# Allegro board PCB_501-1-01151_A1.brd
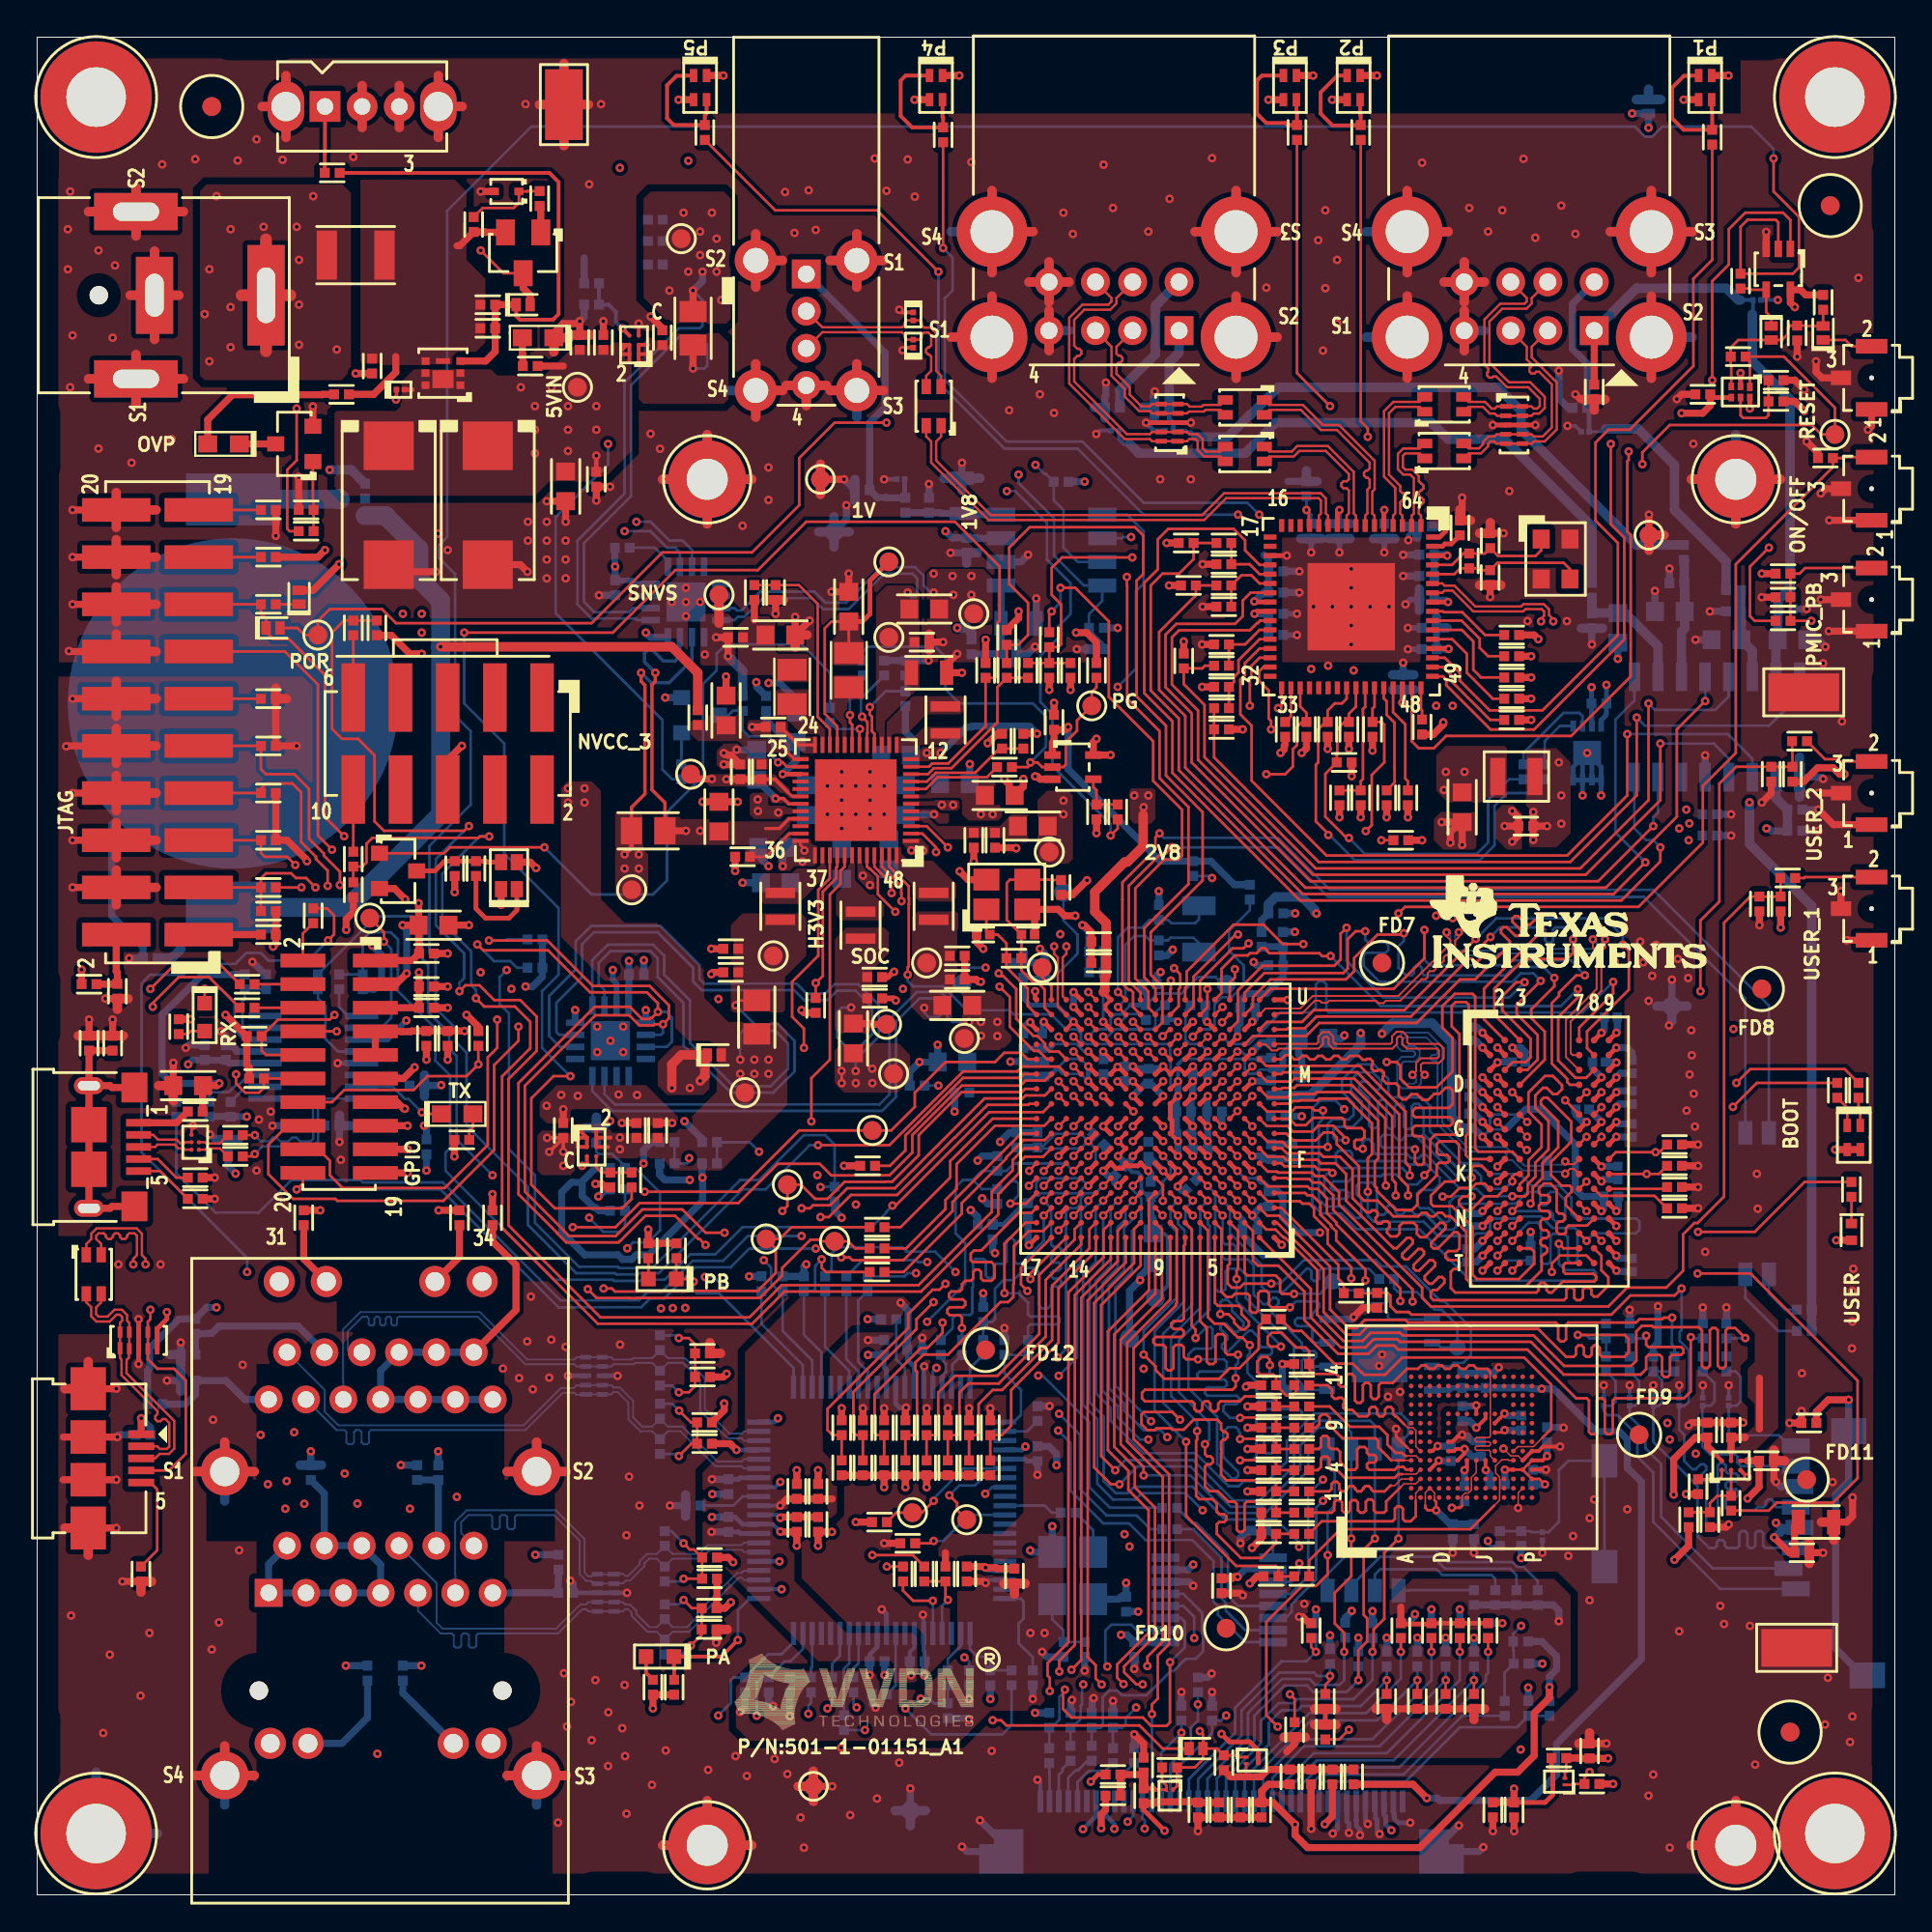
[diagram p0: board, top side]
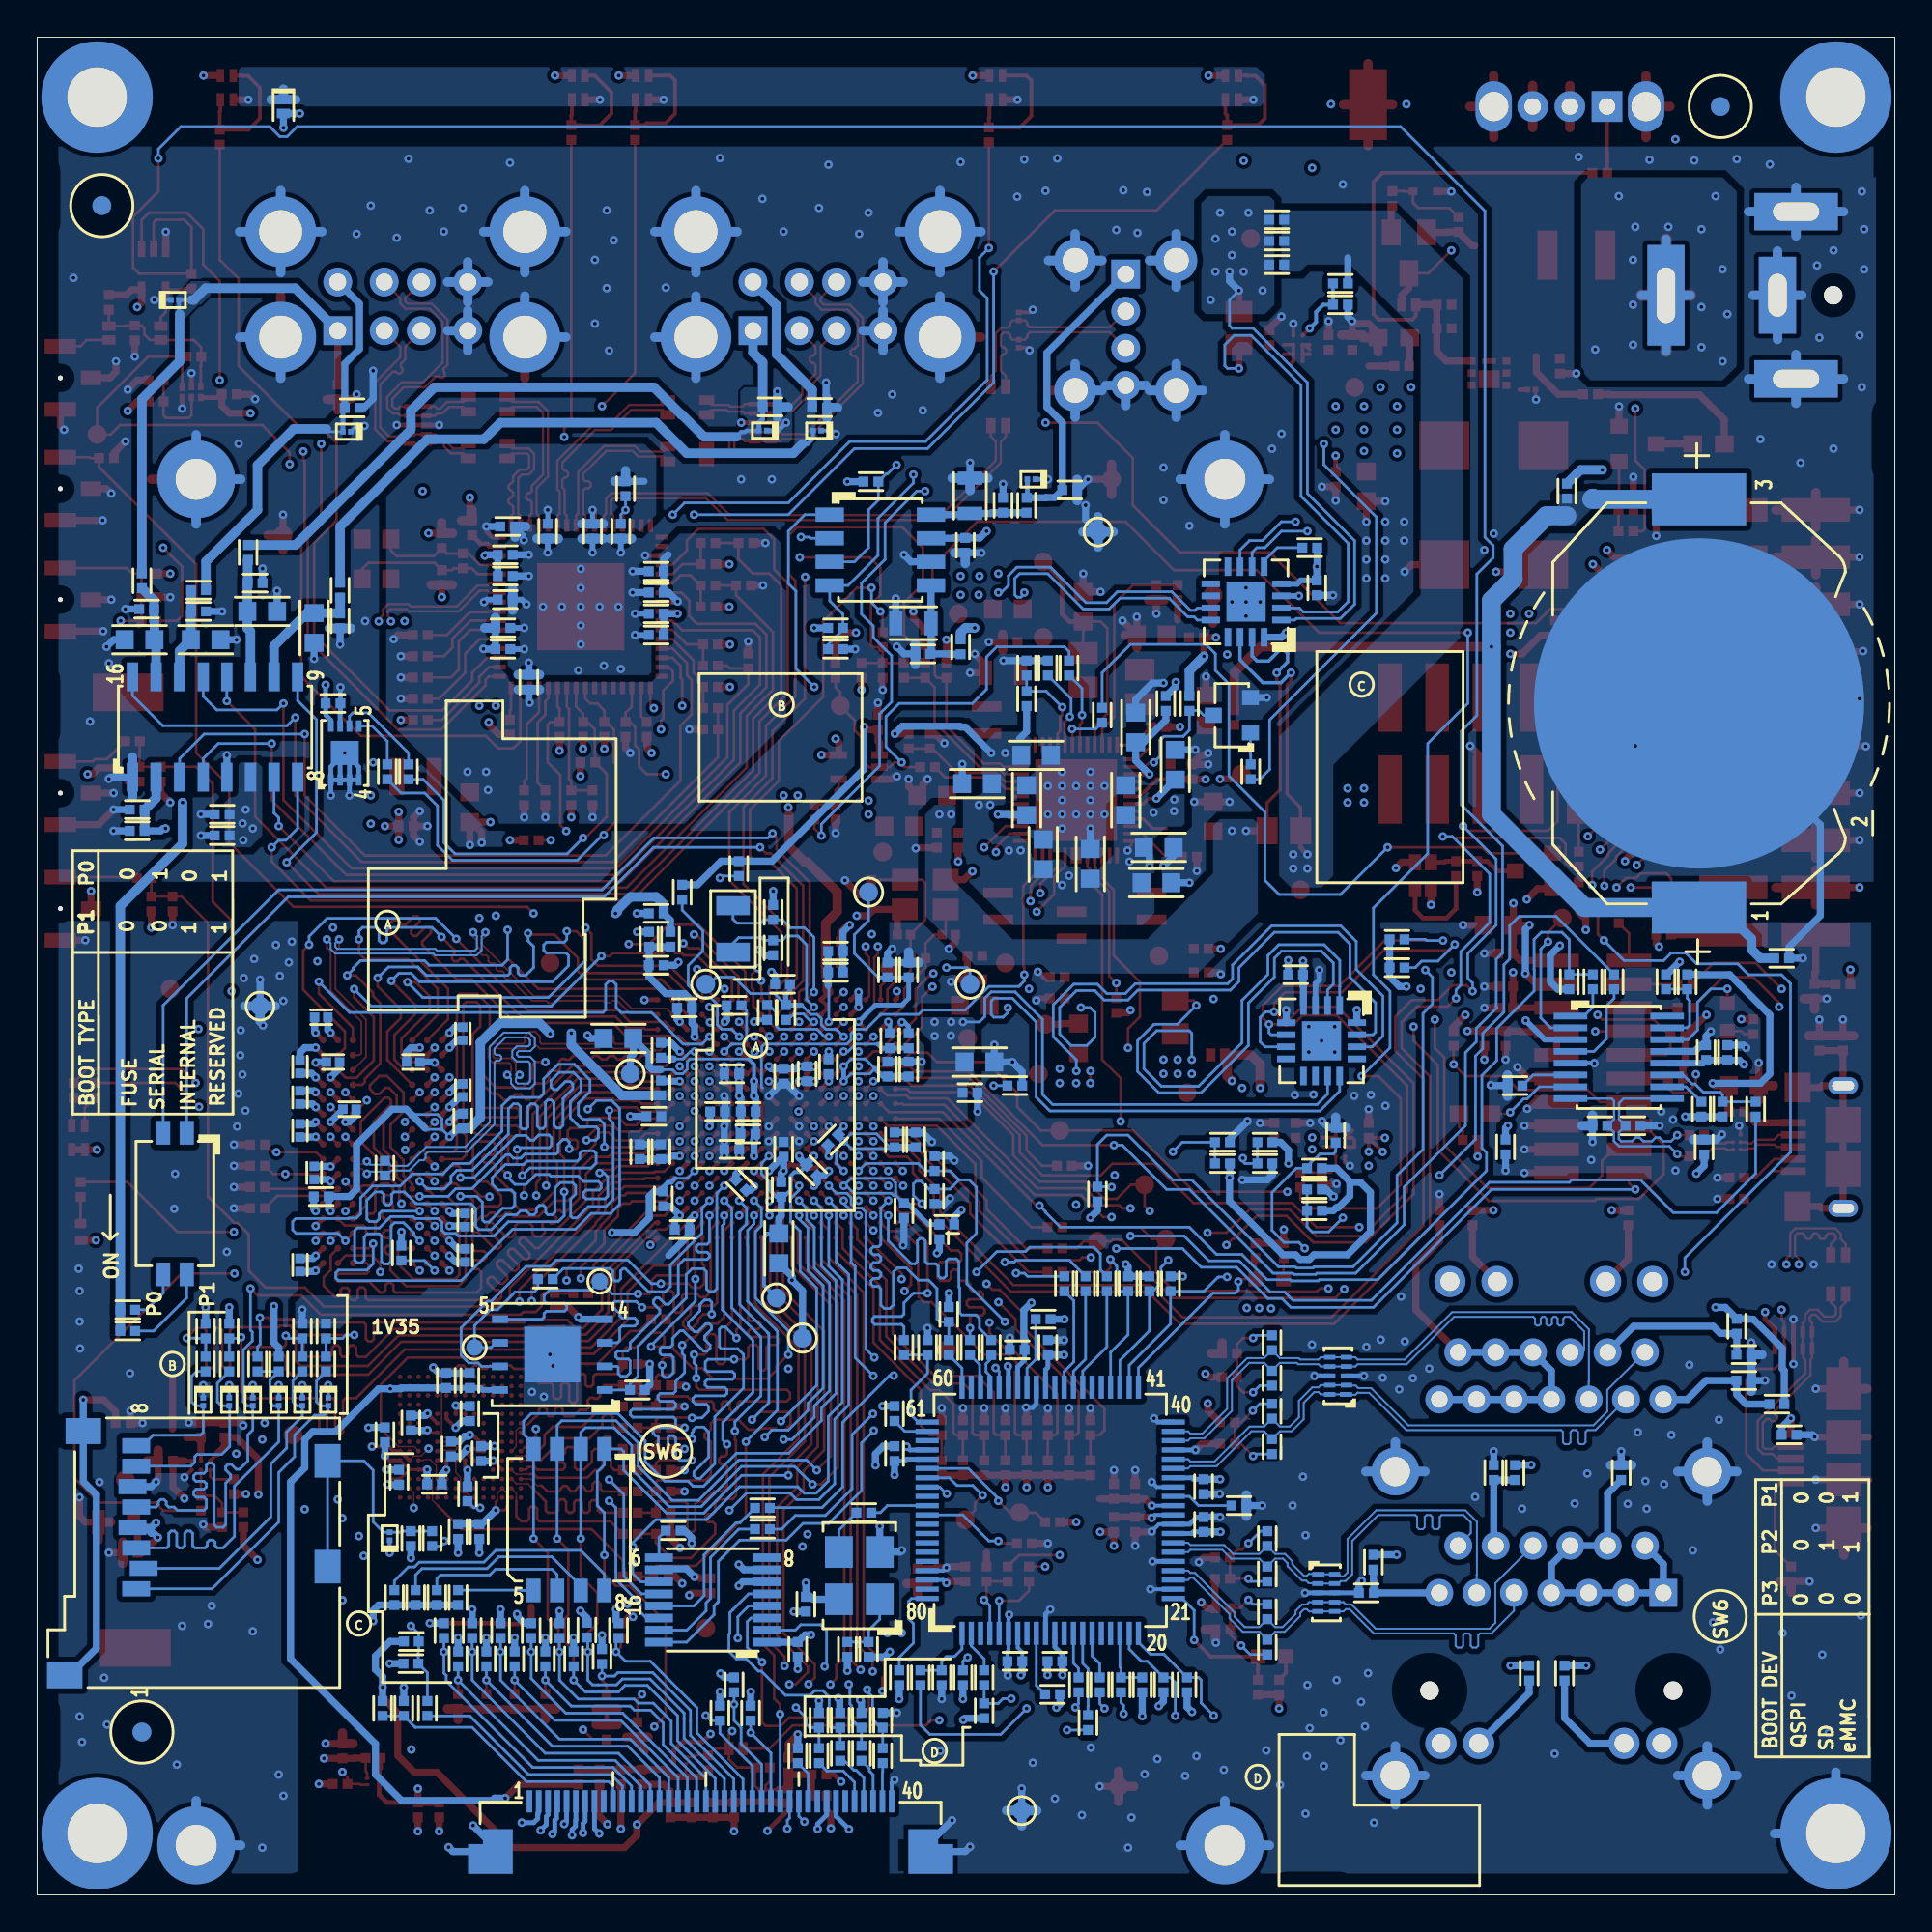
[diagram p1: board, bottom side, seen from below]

Outline 100 x 100 mm; copper layers: TOP, L2_GND, L3_SIG1, L4_SIG2, L5_PWR, BOTTOM. Coordinates in mm from the lower left corner of the outline.
Outline path: 0,100 100,100 100,0 0,0 0,100

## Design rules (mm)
constraint set DEFAULT: min track width 0.142, pair gap 0.152
net group CMD: nets CMD SD2_CMD
net group CRS_DV_A: nets CRS_DV_A PHYA_CRSDV
net group CRS_DV_B: nets CRS_DV_B PHYB_CRSDV
net group DAT0: nets DAT0 SD2_DATA0
net group DAT1: nets DAT1 SD2_DATA1
net group DAT2: nets DAT2 SD2_DATA2
net group DAT3: nets DAT3 SD2_DATA3
net group DAT4: nets DAT4 SD2_DATA4
net group DAT5: nets DAT5 SD2_DATA5
net group DAT6: nets DAT6 SD2_DATA6
net group DAT7: nets DAT7 SD2_DATA7
net group DEBUG_: nets DEBUG_DN DEBUG_DP
net group DEBUG_USB_: nets DEBUG_USB_DN DEBUG_USB_DP
net group DRAM_SDCLK0: nets DRAM_SDCLK0_N DRAM_SDCLK0_P
net group DRAM_SDQS0: nets DRAM_SDQS0_N DRAM_SDQS0_P
net group DRAM_SDQS1: nets DRAM_SDQS1_N DRAM_SDQS1_P
net group OTG_: nets OTG_DM OTG_DP
net group PHYA_MDI_1: nets PHYA_MDI_1_N PHYA_MDI_1_P
net group PHYA_MDI_2: nets PHYA_MDI_2_N PHYA_MDI_2_P
net group PHYA_RXD0: nets PHYA_RXD0 RXD0_A
net group PHYA_RXD1: nets PHYA_RXD1 RXD1_A
net group PHYA_TX_EN: nets ENET1_TXEN PHYA_TX_EN
net group PHYA_TXD0: nets ENET1_TXD0 PHYA_TXD0
net group PHYA_TXD1: nets ENET1_TXD1 PHYA_TXD1
net group PHYB_MDI_1: nets PHYB_MDI_1_N PHYB_MDI_1_P
net group PHYB_MDI_2: nets PHYB_MDI_2_N PHYB_MDI_2_P
net group PHYB_RXD0: nets PHYB_RXD0 RXD0_B
net group PHYB_RXD1: nets PHYB_RXD1 RXD1_B
net group PHYB_TX_EN: nets ENET2_TXEN PHYB_TX_EN
net group PHYB_TXD0: nets ENET2_TXD0 PHYB_TXD0
net group PHYB_TXD1: nets ENET2_TXD1 PHYB_TXD1
net group QSPIA_SCLK: nets QSPIA_SCLK ST_QSPIA_SCLK
net group SD1_CD#: nets SD1_CD# SD1_CD#_R
net group SD1_CLK: nets SD1_CLK SD1_CLK_R
net group SD1_CMD: nets SD1_CMD SD1_CMD_R
net group SD2_CLK: nets SD2_CLK ST_SD2_CLK
net group SDCARD_DAT0: nets SD1_DATA0 SDCARD_DAT0
net group SDCARD_DAT1: nets SD1_DATA1 SDCARD_DAT1
net group SDCARD_DAT2: nets SD1_DATA2 SDCARD_DAT2
net group SDCARD_DAT3: nets SD1_DATA3 SDCARD_DAT3
net group USB: nets USBDN USBDP
net group USB_FL2: nets USBDM_FL2 USBDP_FL2
net group USB_FL3: nets USBDM_FL3 USBDP_FL3
net group USB_FL4: nets USBDM_FL4 USBDP_FL4
net group USB_FL5: nets USBDM_FL5 USBDP_FL5
net group USB_OTG1_: nets USB_OTG1_DN USB_OTG1_DP
net group USB_OTG2_: nets USB_HOST_DN USB_HOST_DP
net group USBD: nets USBDN1_DM USBDN1_DP
net group USBD2: nets USBDM_FL1 USBDP_FL1
net group USBDN2_: nets USBDN2_DM USBDN2_DP
net group USBDN3_: nets USBDN3_DM USBDN3_DP
net group USBDN4_: nets USBDN4_DM USBDN4_DP
net group USBDN5_: nets USBDN5_DM USBDN5_DP
net group 50OHM_2W: nets SD1_VSEL SD2_STROBE SD_VSEL_R STBY_REQ TOUCH_BUSY TOUCH_CS# TOUCH_INTR_REQ# TOUCH_MISO TOUCH_MOSI TOUCH_X+ TOUCH_X- TOUCH_XL TOUCH_XR TOUCH_Y+ TOUCH_Y- TOUCH_YD TOUCH_YU USR_LED1 USR_LED2 USR_LED3
net group CLOCK: nets ENET_REF_CLK JTAG_DACK JTAG_RTCK JTAG_TCK TOUCH_CLOCK
net group DDR_ADDRESS1: nets DRAM_ADDR0 DRAM_ADDR1 DRAM_ADDR2 DRAM_ADDR3 DRAM_ADDR4 DRAM_ADDR5 DRAM_ADDR6 DRAM_ADDR7 DRAM_ADDR8 DRAM_ADDR9 DRAM_ADDR10 DRAM_ADDR11 DRAM_ADDR12 DRAM_ADDR13 DRAM_ADDR14 DRAM_ADDR15 DRAM_CAS# DRAM_CS0# DRAM_CS1# DRAM_ODT0 DRAM_ODT1 DRAM_RAS# DRAM_RESET# DRAM_SDBA0 DRAM_SDBA1 DRAM_SDBA2 DRAM_SDCKE0 DRAM_SDCKE1 DRAM_SDWE#
net group DDR_BYTE(0-7): nets DRAM_DATA0 DRAM_DATA1 DRAM_DATA2 DRAM_DATA3 DRAM_DATA4 DRAM_DATA5 DRAM_DATA6 DRAM_DATA7 DRAM_DQM0
net group DDR_BYTE(8-15): nets DRAM_DATA8 DRAM_DATA9 DRAM_DATA10 DRAM_DATA11 DRAM_DATA12 DRAM_DATA13 DRAM_DATA14 DRAM_DATA15 DRAM_DQM1
net group DEFAULT: nets BASE_CC# BOOST0 BOOST1 BOOT_MODE0 BOOT_MODE1 BUSY CCM_PMIC_STBY_REQ CLOCK_50MHZ COLL_CC# CS# CSENS2_A0 DC34_SEL DC_SW DC_SW_CTL DDR_ZQPAD DEBUG_5V0 DEBUG_RESET# DEBUG_RXD DEBUG_TXD DEBUG_UART_RESET# DRAM_VREF DRAM_ZQPAD ED_EN_A ED_EN_B EEPR_SCL EEPR_SDA ENET_INT_A ENET_INT_B ENETPHY_RESET# EXT_EN FB_DCDC6 FT230_CTS# FT230_RTS# GANG_EN GATE_PMOS GND_DEBUGUSB_CONN GPANIO GPIO1_IO22 GPIO1_IO24 GPIO1_IO25 GPIO3_IO03 GPIO5_IO02 GPIO5_IO03 GPIO5_IO04 GPIO5_IO05 GPIO5_IO06 GPIO5_IO07 GPIO5_IO08 GPIO5_IO09 HUB_CFG_SEL1 HUB_CFG_SEL2 HUB_LEDA1# HUB_LEDA2# HUB_LEDA3# HUB_LEDA4# HUB_LEDA5# HUB_OCS1# HUB_OCS2# HUB_OCS3# HUB_OCS4# HUB_OCS5# HUB_PWR_EN1 HUB_PWR_EN2 HUB_PWR_EN3 HUB_PWR_EN4 HUB_PWR_EN5 HUB_RESET# HUB_VDDA18PLL HUB_VDDDIG18 I2C2_CURSENSE_SCL I2C2_CURSENSE_SDA I2C4_HUB_EEPR_SCL I2C4_HUB_EEPR_SDA I2C4_SCL I2C4_SDATA I.MX_ONOFF INT_LDO IOVDD_LCD IOVDD_LCD_SW_IN JTAG_DE JTAG_MOD JTAG_PWR JTAG_SRST# JTAG_TDI JTAG_TDO JTAG_TMS JTAG_TRST# JTAG_VREF LCD_CS# LCD_IM0 LCD_PWR_EN LCD_RESET# LED_ACT/COL_A LED_ACT/COL_B LED_LINK_A LED_LINK_B LED_SPEED_A LED_SPEED_B LOCAL_PWR MII_MODE_A MII_MODE_B N20222589 N20248573 N20257520 N20264538 N20269907 N20274074 N20274097 N20280334 N20280345 N20323615 N20326291 N20327026 N20327568 N20327935 N20368037 N20387129 N20387131 N20387133 N20387143 N20387145 N20387147 N20429331 N20436944 N20467513 N20496187 N20630241 N20829804 N20866761 N20868982 NVCC_DRAM_1V35 NVCC_DRAM_1V35_SNS NVCC_LCD NVCC_PLL ON_LS4 ON_LS5 OVRPRTC OVRPRTC_LED OVRPRTC_LED_PWR PB_RESET PFBIN PFO# PGOOD PGOOD_BU PHY_MDC PHY_MDIO PMIC_AC_DET PMIC_CC PMIC_GPIO1 PMIC_I2C1_SCL PMIC_I2C1_SDA PMIC_IN_CC# PMIC_INT# PMIC_PB PMIC_PB_B PMIC_PFI PMIC_PFO# PMIC_PGOOD PMIC_PWR_EN PMIC_PWR_EN_R PMIC_STBY_REQ PMIC_WAKE# POR_B PRTDIS_M6 PRTDIS_M7 PRTDIS_P6 PRTDIS_P7 PWR_OV_BASE PWR_OV_CTL PWR_OVP_LED RBIAS RBIAS_HUB RES# RES_LED1 RES_LED2 RES_LED3 REV_CHANGE REVRES_1 REVRES_2 RTC_XTALI RTC_XTALO RXER_A RXER_B RXLED ST_HUB_LEDA1# ST_HUB_LEDA2# ST_HUB_LEDA3# ST_HUB_LEDA4# ST_HUB_LEDA5# SYS_BU SYS_NRST TPS2054_OC1# TPS2054_OC2# TPS2054_OC3# TPS2054_OC4# TXLED UART1_CTS# UART1_RX_DATA UART1_TX_DATA USB2ANY_I2C_SCL USB2ANY_I2C_SDA USB_HOST_ID USB_LDO_DECAP USB_OTG1_CHD# USB_OTG1_FAULT# USB_OTG1_ID USB_OTG1_PWREN USR_B0 USR_B1 USR_BT0 USR_BT1
net group DEFAULT_50E: nets VBUS_DET VBUS_DET_HUB WDOG_ANY X1_ENETPHY XTALI XTALIN_HUB XTALO XTALOUT_HUB
net group EMMC_SIG: nets SD2_RESET#
net group LCD: nets LCD_DATA0 LCD_DATA1 LCD_DATA2 LCD_DATA3 LCD_DATA4 LCD_DATA5 LCD_DATA6 LCD_DATA7 LCD_DATA8 LCD_DATA9 LCD_DATA10 LCD_DATA11 LCD_DATA12 LCD_DATA13 LCD_DATA14 LCD_DATA15 LCD_DATA/COMND LCD_RD_E# LCD_WR_E#
net group LCD2: nets LCD_DATA16 LCD_DATA17 LCD_DATA18 LCD_DATA19 LCD_DATA20 LCD_DATA21 LCD_DATA22 LCD_DATA23
net group PHY_A: nets PHYA_RXER
net group PHY_B: nets PHYB_RXER
net group PWR: nets 3V3_OUT 5VIN DCDC1_L1 DCDC2_L2 DCDC3_L3 DCDC4_L4A DCDC4_L4B DCDC5_L5 DCDC6_L6 N20681531 N20684634 N20685468 N20685796 OTG_PWR VBUS1_FL VBUS2_FL VBUS3_FL VBUS4_FL VBUS5_FL VBUS_DEBUG_USB_5V VCCI_EMMC VDD_1V0 VDD_1V8 VDD_1V8_SNS VDD_ARM_CAP VDD_CENT_TAP_A1 VDD_CENT_TAP_A2 VDD_CENT_TAP_B1 VDD_CENT_TAP_B2 VDD_COINCELL_IN VDD_DCDC6 VDD_ETH_ANA_3V3 VDD_EXT_LS_5V0 VDD_EXT_LS_5V0_SNS VDD_HIGH_CAP VDD_HIGH_IN_3V3 VDD_HIGH_IN_3V3_SNS VDD_HUB_LED VDD_IN_BU VDD_LCD VDD_LCD_BCKLIGHT VDD_LCD_SW_IN VDD_LDO1 VDD_LDO_2V8 VDD_NVCC_3V3 VDD_NVCC_SD1 VDD_OTG1_VBUS VDD_PERI_3V3 VDD_PERI_FIL_3V3 VDD_PMIC_LS_5V0 VDD_PMIC_LS_5V0_SNS VDD_SNVS_CAP VDD_SNVS_IN VDD_SOC_ARM_IN VDD_SOC_ARM_IN_SNS VDD_SOC_CAP VDD_USB_VBUS1 VDD_USB_VBUS2 VDD_USB_VBUS3 VDD_USB_VBUS4 VDD_USB_VBUS5 VIN_PMIC_5V0 VREF_TOUCH_C
net group QSPIA_SIG: nets QSPIA_DATA0 QSPIA_DATA1 QSPIA_DATA2 QSPIA_DATA3 QSPIA_SS0#

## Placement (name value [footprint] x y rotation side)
BH1  BK-912  [BAT3_21P97_21P08X15P24_A1]  10.54 64.13 90 bottom
C1  0.1uF  [0402]  18.03 82.3 270 top
C2  0.01uF  [0402]  24.26 85.6 0 top
C3  100uF  [TCAP_CASED]  24.26 74.8 270 top
C4  22uF  [0603]  28.45 75.82 270 top
C5  1uF  [0402]  30.1 76.2 270 top
C6  4.7uF  [0603]  39.75 54.48 180 bottom
C7  10uF  [0402]  49.53 50.55 0 top
C8  0.1uF  [0402]  49.53 49.28 0 top
C9  0.1uF  [0402]  45.09 48.26 0 top
C10  10uF  [0402]  37.34 50.93 180 top
C11  0.1uF  [0402]  37.34 49.66 180 top
C12  4.7uF  [0603]  45.85 56.01 90 bottom
C13  4.7uF  [0603]  46.23 61.34 180 bottom
C14  4.7uF  [0603]  43.31 55.5 90 bottom
C15  4.7uF  [0603]  39.62 56.39 180 bottom
C16  4.7uF  [0603]  49.4 59.82 0 bottom
C17  4.7uF  [0603]  41.4 58.93 90 bottom
C18  10uF  [0402]  45.09 49.4 0 top
C19  47uF  [0805_B_A1]  48.01 65.79 0 top
C20  0.1uF  [0402]  47.62 67.44 0 top
C21  10uF  [0402]  50.42 56.77 270 top
C22  0.1uF  [0402]  51.56 56.77 270 top
C23  22uF  [0603]  51.82 59.18 0 top
C24  22uF  [0603]  36.7 58.04 90 top
C26  10uF  [0402]  38.99 60.45 90 top
C27  4.7uF  [0603]  46.74 58.93 90 bottom
C28  4.7uF  [0603]  38.73 60.83 90 bottom
C29  0.1uF  [0402]  37.85 60.45 90 top
C30  22uF  [0603]  43.69 69.34 90 top
C31  22uF  [0603]  40.01 67.82 0 top
C32  4.7uF  [0603]  37.08 63.75 90 top
C33  1uF  [0402]  39.62 62.87 180 top
C34  0.1uF  [0402]  37.97 55.88 180 top
C35  10uF  [0402]  33.4 41.15 90 top
C36  1uF  [0402]  32.26 41.15 90 top
C37  4.7uF  [0402]  6.1 50.42 180 bottom
C38  0.1uF  [0402]  28.32 41.15 90 top
C39  2.2uF  [0402]  93.09 23.37 0 top
C40  2.2uF  [0402]  89.92 25.02 90 top
C41  10uF  [0402]  29.21 83.57 90 top
C42  1uF  [0402]  91.19 25.02 90 top
C43  1uF  [0402]  33.66 83.82 90 top
C44  22uF  [0603]  49.28 44.83 180 bottom
C45  0.22uF  [0402]  59.82 44.07 90 bottom
C46  0.22uF  [0402]  59.94 37.97 90 bottom
C47  0.22uF  [0402]  58.29 38.99 225 bottom
C48  22uF  [0603]  60.07 34.8 270 bottom
C49  4.7uF  [0402]  49.78 43.18 180 bottom
C50  0.22uF  [0402]  59.82 40.13 270 bottom
C51  0.22uF  [0402]  61.72 42.16 0 bottom
C52  0.22uF  [0402]  61.74 40.96 0 bottom
C53  0.22uF  [0402]  58.55 44.2 90 bottom
C54  22uF  [0603]  68.71 46.1 0 bottom
C55  4.7uF  [0402]  54.1 45.97 90 bottom
C56  0.22uF  [0402]  53.09 45.97 90 bottom
C57  10uF  [0402]  54.23 49.78 90 bottom
C58  0.22uF  [0402]  53.09 49.78 90 bottom
C59  0.22uF  [0402]  59.88 49.02 0 bottom
C60  10uF  [0402]  59.69 47.5 270 bottom
C61  0.22uF  [0402]  60.71 47.5 270 bottom
C62  0.22uF  [0402]  57.4 44.58 270 bottom
C63  0.22uF  [0402]  84.71 37.59 0 bottom
C64  0.22uF  [0402]  77.09 41.66 90 bottom
C65  10uF  [0402]  66.8 41.91 0 bottom
C66  0.22uF  [0402]  63.37 42.16 0 bottom
C67  0.22uF  [0402]  67.56 40.01 270 bottom
C68  0.22uF  [0402]  66.42 40.01 270 bottom
C69  0.22uF  [0402]  62.61 40.13 180 bottom
C70  0.22uF  [0402]  62.61 44.2 180 bottom
C71  0.22uF  [0402]  66.42 43.43 90 bottom
C72  0.22uF  [0402]  62.48 47.88 0 bottom
C73  0.22uF  [0402]  65.15 47.75 0 bottom
C74  1uF  [0201]  76.96 34.42 90 bottom
C75  1uF  [0201]  85.09 38.86 90 bottom
C76  1uF  [0201]  83.19 42.29 0 bottom
C77  1uF  [0201]  85.85 41.15 90 bottom
C78  0.1uF  [0201]  84.71 47.24 0 bottom
C79  0.1uF  [0201]  84.07 44.83 180 bottom
C80  0.1uF  [0201]  85.85 42.93 270 bottom
C81  0.1uF  [0201]  76.96 36.32 90 bottom
C82  0.1uF  [0201]  77.09 43.31 90 bottom
C83  0.1uF  [0201]  77.09 46.35 270 bottom
C84  0.1uF  [0201]  85.85 44.58 90 bottom
C85  0.1uF  [0201]  85.85 33.91 270 bottom
C86  0.1uF  [0201]  79.76 44.83 0 bottom
C87  4.7uF  [0402]  66.68 52.83 0 bottom
C88  0.1uF  [0402]  66.68 50.04 180 bottom
C89  0.22uF  [0402]  53.34 36.83 270 bottom
C90  0.22uF  [0402]  62.11 38.21 45 bottom
C91  0.22uF  [0402]  57.15 40.64 315 bottom
C92  0.22uF  [0402]  65.28 35.81 0 bottom
C93  18pF  [0402]  72.14 32 270 top
C94  10uF  [0402]  57.15 51.31 180 top
C95  10uF  [0402]  57.15 50.16 180 top
C96  0.22uF  [0402]  66.29 37.47 270 bottom
C97  10uF  [0402]  57.02 50.8 180 bottom
C98  0.1uF  [0402]  57.02 49.66 180 bottom
C99  0.22uF  [0402]  52.7 40.64 90 bottom
C100  10uF  [0402]  53.09 44.45 90 bottom
C101  0.1uF  [0402]  54.23 44.45 90 bottom
C102  0.22uF  [0402]  53.85 40.64 90 bottom
C103  0.1uF  [0402]  77.72 24 90 bottom
C104  0.1uF  [0402]  79.88 25.4 270 bottom
C105  2.2uF  [0402]  76.71 25.91 90 bottom
C106  0.1uF  [0402]  76.1 23.75 270 bottom
C107  0.1uF  [0402]  81.28 24.77 90 bottom
C108  0.1uF  [0402]  78.61 22.1 180 bottom
C109  2.2uF  [0402]  80.52 22.48 90 bottom
C110  1uF  [0402]  77.34 19.56 270 bottom
C111  0.1uF  [0402]  76.2 19.56 270 bottom
C112  10uF  [0402]  76.71 27.69 90 bottom
C113  0.22uF  [0402]  77.98 27.69 90 bottom
C114  47uF  [0805_B_A1]  95.76 20.07 0 top
C115  0.1uF  [0402]  95 18.41 0 top
C116  0.1uF  [0402]  40.89 19.94 270 top
C117  10uF  [0402]  52.61 17.16 90 top
C118  0.1uF  [0402]  45.21 12.57 0 bottom
C119  0.1uF  [0402]  53.85 23.75 90 bottom
C120  0.1uF  [0402]  50.04 17.27 90 top
C121  0.1uF  [0402]  45.59 29.46 90 bottom
C122  0.1uF  [0402]  28.45 16.26 180 bottom
C123  0.1uF  [0402]  21.59 22.73 270 bottom
C124  0.1uF  [0402]  8.13 27.69 0 bottom
C125  0.1uF  [0402]  8.13 29.08 0 bottom
C126  10uF  [0402]  40.89 21.72 90 top
C127  0.1uF  [0402]  42.04 21.72 90 top
C128  0.1uF  [0402]  84.07 64.13 180 bottom
C129  33pF  [0402]  78.22 72.9 90 top
C130  33pF  [0402]  78.21 70.91 270 top
C131  1uF  [0402]  66.68 71.25 0 bottom
C132  1uF  [0402]  74.8 72.14 180 bottom
C133  0.1uF  [0402]  66.68 70.1 0 bottom
C134  0.1uF  [0402]  74.8 70.99 180 bottom
C135  1uF  [0402]  66.68 67.82 0 bottom
C136  0.1uF  [0402]  66.68 68.96 0 bottom
C137  0.1uF  [0402]  73.53 65.28 90 bottom
C138  0.1uF  [0402]  74.68 73.66 180 bottom
C139  0.1uF  [0402]  70.1 73.41 270 bottom
C140  0.1uF  [0402]  74.8 69.72 180 bottom
C141  0.1uF  [0402]  74.93 67.06 180 bottom
C142  0.1uF  [0402]  72.52 73.41 270 bottom
C143  1uF  [0402]  74.93 68.2 180 bottom
C149  22uF  [0603]  94.49 67.56 0 bottom
C150  0.1uF  [0402]  94.11 69.22 0 bottom
C151  22uF  [0603]  90.93 67.56 180 bottom
C152  0.1uF  [0402]  91.31 69.09 180 bottom
C153  22uF  [0603]  87.88 69.09 180 bottom
C154  0.1uF  [0402]  88.26 70.61 180 bottom
C155  22uF  [0603]  85.09 68.2 270 bottom
C156  0.1uF  [0402]  83.69 68.58 270 bottom
C157  10uF  [0402]  94.62 57.28 0 bottom
C158  0.1uF  [0402]  94.62 58.42 0 bottom
C159  10uF  [0402]  90.04 57.02 0 bottom
C160  0.1uF  [0402]  90.04 58.17 0 bottom
C161  0.1uF  [0402]  63.75 65.02 180 top
C162  0.1uF  [0402]  63.75 67.31 180 top
C163  0.1uF  [0402]  63.88 69.34 180 top
C164  0.1uF  [0402]  63.88 71.63 180 top
C165  0.1uF  [0402]  50.04 72.64 270 bottom
C166  47uF  [0805_B_A1]  49.78 75.31 90 bottom
C167  0.1uF  [0402]  48.01 74.8 270 bottom
C168  47uF  [0805_B_A1]  52.83 68.45 0 bottom
C169  0.1uF  [0402]  52.32 66.8 180 bottom
C170  0.1uF  [0402]  9.02 45.34 90 bottom
C171  0.1uF  [0402]  10.16 45.34 90 bottom
C172  4.7uF  [0402]  20.96 40.26 270 bottom
C173  0.1uF  [0402]  10.27 40.25 90 bottom
C174  4.7uF  [0603]  8.13 43.56 180 top
C175  47pF  [0402]  15.88 41.4 0 bottom
C176  47pF  [0402]  14.1 41.4 180 bottom
C177  0.1uF  [0402]  4.06 45.85 90 top
C180  0.1uF  [0402]  32.26 49.53 0 bottom
C181  0.1uF  [0402]  31.12 70.36 270 bottom
C182  4.7uF  [0402]  62.48 4.57 270 top
C183  4.7uF  [0402]  65.91 4.57 270 top
C184  10uF  [0402]  59.56 6.98 90 top
C185  0.1uF  [0402]  63.63 4.57 270 top
C186  10uF  [0402]  68.58 6.35 270 top
C187  0.1uF  [0402]  64.77 4.57 270 top
C188  0.22uF  [0402]  59.05 13.21 270 bottom
C189  0.1uF  [0402]  65.76 19.61 0 bottom
C190  0.1uF  [0402]  63.75 16.64 270 top
C191  18pF  [0402]  57.91 9.4 270 bottom
C192  18pF  [0402]  55.63 9.4 270 bottom
C193  18pF  [0402]  54.48 9.4 270 bottom
C194  18pF  [0402]  56.77 9.4 270 bottom
C195  1uF  [0402]  92.71 53.34 270 top
C196  1uF  [0402]  93.34 60.32 270 top
C197  4.7uF  [0402]  78.36 4.57 270 top
C198  10uF  [0402]  83.57 7.75 90 top
C199  0.1uF  [0402]  79.5 4.57 270 top
C200  15pF  [0402]  60.38 50.98 270 bottom
C201  15pF  [0402]  60.38 52.89 90 bottom
C204  12pF  [0201]  53.34 51.69 0 top
C205  12pF  [0201]  50.93 51.69 180 top
C572  0.1uF  [0402]  4.32 48.64 270 top
C573  0.1uF  [0402]  89.66 80.77 180 top
C574  0.1uF  [0402]  47.24 29.34 0 bottom
C575  0.1uF  [0402]  37.21 19.94 90 bottom
C576  0.1uF  [0402]  37.21 21.97 270 bottom
C577  0.1uF  [0402]  47.37 12.57 0 bottom
C583  4.7uF  [0603]  21.34 52.2 0 top
C584  0.1uF  [0402]  20.96 50.67 0 top
C585  1uF  [0402]  20.96 48.9 0 top
C586  0.1uF  [0402]  20.96 47.75 0 top
C587  1uF  [0402]  22.1 46.1 270 top
C588  0.1uF  [0402]  20.96 46.1 270 top
C589  4.7uF  [0603]  76.71 58.55 270 top
C590  220uF  [TCAP_CASEE]  18.92 74.8 270 top
C591  0.1uF  [0402]  36.2 18.16 180 top
C592  0.1uF  [0402]  36.17 14.29 180 top
C593  0.1uF  [0402]  35.92 24.29 180 top
C594  0.1uF  [0402]  35.81 29.15 180 top
C596  1uF  [0402]  30.48 83.57 90 top
C597  10uF  [0402]  80.14 57.53 180 top
C598  0.1uF  [0402]  96.27 77.34 180 top
C599  0.1uF  [0402]  94.74 84.07 270 top
C600  4.7uF  [0603]  40.86 62.84 90 bottom
C601  0.1uF  [0402]  83.82 80.9 90 top
C602  0.1uF  [0402]  83.04 80.04 0 bottom
C603  0.1uF  [0402]  60.54 80.1 0 bottom
C604  0.1uF  [0402]  57.88 80.06 0 bottom
C605  0.1uF  [0402]  44.41 75.62 0 bottom
C606  0.1uF  [0402]  5.7 24.77 0 bottom
C607  0.01uF  [0402]  58.62 15.65 270 bottom
D1  MM5Z5V1S  [DIO_SOD-523_A1]  25.27 91.69 180 top
D2  CDBQR0130L  [DIO-0402]  26.16 85.6 0 top
D4  R  [LED-0603]  10.03 78.1 180 top
D5  G  [LED-0603]  26.97 83.82 180 top
D6  CDBQR0130L  [DIO-0402]  36.45 45.21 0 top
D7  Y  [LED-0603_C_A1]  33.53 12.83 180 top
D8  Y  [LED-0603_C_A1]  33.66 33.15 180 top
D9  CDBQR0130L  [DIO-0402]  86.74 96.27 270 bottom
D10  G  [LED-0603]  22.61 42.04 0 top
D11  Y  [LED-0603_C_A1]  9.02 47.24 270 top
D12  CDBQR0130L  [DIO-0402]  62.38 7.87 0 top
D15  O  [LED2_0P9_1X0P6]  97.66 35.69 90 top
D26  CDBQR0130L  [DIO-0402]  12.7 68.2 0 top
D27  CDBQR0130L  [DIO-0402]  96.14 84.07 90 top
D28  CDBQR0130L  [DIO-0402]  93.34 84.07 270 top
D29  CDBQR0130L  [DIO-0402]  14.1 69.85 90 top
DA1  HSMF-C165  [LED4_0P7_1P6X0P8]  89.79 97.28 90 top
DA2  HSMF-C165  [LED4_0P7_1P6X0P8]  70.87 97.28 90 top
DA3  HSMF-C165  [LED4_0P7_1P6X0P8]  67.44 97.28 90 top
DA4  HSMF-C165  [LED4_0P7_1P6X0P8]  48.39 97.28 90 top
DA5  HSMF-C165  [LED4_0P7_1P6X0P8]  35.69 97.28 90 top
DA6  HSMF-C165  [LED4_0P7_1P6X0P8]  97.79 40.77 90 top
DA8  LTST-C195TBKFKT-2A  [LED4_0P85_1P5X1P6]  25.4 54.86 180 top
F1  6A, 6V DC  [FUSE_1210_A1]  17.14 88.26 0 top
FB1  120E  [0402]  42.04 19.94 90 top
FB3  120E  [0402]  50.29 67.18 90 bottom
FB4  120E  [0402]  8.51 42.16 0 top
FB5  120E  [0402]  8.51 37.47 0 top
FB6  120E  [0402]  69.72 6.35 90 top
FB7  120E  [0402]  57.91 6.48 0 top
FB8  120E  [0402]  70.87 6.35 90 top
FB9  120E  [0402]  57.91 5.33 0 top
FB10  120E  [0402]  94.36 70.74 90 bottom
FB11  120E  [0402]  91.31 70.23 180 bottom
FB12  120E  [0402]  88.65 72.26 90 bottom
FB13  120E  [0402]  83.69 70.23 90 bottom
FB14  120E  [0402]  46.74 74.8 90 bottom
FB15  120E  [0402]  5.59 17.27 90 top
FB16  120E  [0402]  95.38 25.4 0 top
FB17  120E  [0402]  28.07 17.91 270 bottom
FB18  120E  [0402]  20.45 22.73 270 bottom
FB19  120E  [0402]  6.35 26.42 0 bottom
FB20  120E  [0402]  8.51 30.61 270 bottom
FD1  Global  [GFD40_120]  96.52 90.93 0 top
FD2  Global  [GFD40_120]  94.36 8.76 0 top
FD3  Global  [GFD40_120]  9.4 96.27 0 top
FD4  Global  [GFD40_120]  96.52 90.93 180 bottom
FD5  Global  [GFD40_120]  94.36 8.76 180 bottom
FD6  Global  [GFD40_120]  9.4 96.27 180 bottom
FD7  Local  [LFD40_80]  72.39 50.16 0 top
FD8  Local  [LFD40_80]  92.84 48.77 0 top
FD9  Local  [LFD40_80]  86.23 24.77 0 top
FD10  Local  [LFD40_80]  64.01 14.35 0 top
FD11  Local  [LFD40_80]  95.25 22.35 0 top
FD12  Local  [LFD40_80]  51.05 29.34 0 top
FL1  DLW21HN900SQ2L  [CM_CHK4_0P8_2X1P2]  75.74 77.72 0 top
FL2  DLW21HN900SQ2L  [CM_CHK4_0P8_2X1P2]  75.74 80.23 0 top
FL3  DLW21HN900SQ2L  [CM_CHK4_0P8_2X1P2]  65.01 80.07 180 top
FL4  DLW21HN900SQ2L  [CM_CHK4_0P8_2X1P2]  65.01 77.56 180 top
FL5  DLW21HN900SQ2L  [CM_CHK4_0P8_2X1P2]  48.26 80.14 90 top
FL6  DLW21HN900SQ2L  [CM_CHK4_0P8_2X1P2]  3.05 33.4 270 top
H1  HDR_2X5  [CON_HDR_2X5M_2P54_SM_ST]  22.1 61.98 180 top
H4  HDR_2X10  [CON_BERG_2X10M_1P27_SM_ST_A_A1]  16.26 44.58 270 top
H5  HDR_2X10  [CON_HDR_2X10M_2P54_SM_CUST_A1]  6.48 63.12 90 top
J1  CON_PWRJACK  [CON_PWR-JACK_2M_6_TH_RA_A_A1]  12.32 86.11 90 top
J2  CON_MICROSD  [CON_USD_1X1F_12L_1P1_SM_RA]  91.57 18.41 90 bottom
J3  CON_RJ45  [CON_RJ45_2X1_2P01_TH_RA_A1]  12.43 16.26 0 top
J4  CON_USBA  [CON_USB-A_2X1F_2_TH_RA_A1]  83.82 84.2 180 top
J5  CON_USBA  [CON_USB-A_2X1F_2_TH_RA_A1]  61.47 84.2 180 top
J6  CON_USBA  [CON_USB-A_1X1F_2_TH_RA_D_A1]  41.4 87.25 180 top
J7  CON_USB MICRO-AB  [CON_USB_5F_0P65_SM_RA_A2]  5.6 23.5 270 top
J8  CON_USB Micro-B  [CON_USB_1X1-5F_0P65_SM_RA_D_A1]  5.46 40.26 270 top
J9  CON_FPC  [CON_FPC_1X40F_0P5_SM_RA_N_A1]  63.75 5.03 180 bottom
L1  1.5uH  [IND_0806_B_A1]  48.26 53.21 270 top
L2  1.5uH  [IND_0806_B_A1]  44.32 52.2 270 top
L3  1.5uH  [IND_0806_B_A1]  40.01 53.21 270 top
L4  1.5uH  [IND_0806_B_A1]  48.9 63.25 90 top
L5  10uH  [IND-0805_1P45]  43.69 65.92 90 top
L6  10uH  [IND-0805_1P45]  40.64 65.02 90 top
L7  4.7uH  [IND-2520_1_A1]  79.63 60.2 180 top
MH1  126MILS  [MH236D126T_A1]  3.18 96.77 0 top
MH2  126MILS  [MH236D126T_A1]  96.77 3.3 0 top
MH3  126MILS  [MH236D126T_A1]  3.18 3.3 0 top
MH4  126MILS  [MH236D126T_A1]  96.77 96.77 0 top
MH5  87MILS  [MH165D87T_A1]  36.07 76.2 0 top
MH6  87MILS  [MH165D87T_A1]  91.44 2.67 0 top
MH7  87MILS  [MH165D87T_A1]  91.44 76.2 0 top
MH8  87MILS  [MH165D87T_A1]  36.07 2.67 0 top
NOREF  -  []  24.67 91.29 90 top
NOREF#2  -  []  68.3 14.75 0 top
NOREF#3  -  []  50.6 52.6 0 top
NOREF#4  -  []  72.88 57.04 0 top
NOREF#5  -  []  50.58 51.89 0 top
NOREF#6  -  []  32.76 45 90 top
NOREF#7  -  []  92.3 4.58 0 top
NOREF#8  -  []  70.61 62.34 90 top
NOREF#9  -  []  94.09 57.55 0 top
NOREF#10  -  []  30.1 40.49 90 top
NOREF#11  -  []  90.57 57.89 90 top
NOREF#12  -  []  94.6 30.08 90 top
NOREF#13  -  []  70.1 58.65 90 top
NOREF#14  -  []  48.6 60.22 0 top
NOREF#15  -  []  41.4 58.13 90 top
NOREF#16  -  []  3.79 46.37 0 top
NOREF#17  -  []  66.15 42.91 0 top
NOREF#18  -  []  59.67 38.5 0 top
NOREF#19  -  []  0.32 91.11 0 top
NOREF#20  -  []  52.79 57.93 0 top
NOREF#21  -  []  6.32 86.11 90 top
NOREF#22  -  []  77.07 15.48 0 top
NOREF#23  -  []  79.61 57.26 90 top
NOREF#24  -  []  55.35 66.44 0 top
NOREF#25  -  []  -107.37 133.01 0 top
NOREF#26  -  []  44.3 39.24 0 top
NOREF#27  -  []  88.37 72.79 0 top
NOREF#28  -  []  60.43 46.97 0 top
NOREF#29  -  []  74.97 21.39 0 top
NOREF#30  -  []  58.62 15.25 90 top
NOREF#31  -  []  50.65 28.94 0 top
NOREF#32  -  []  65.77 27.16 0 top
NOREF#33  -  []  47.48 17.8 0 top
NOREF#34  -  []  43.31 24.75 90 top
NOREF#35  -  []  49.17 17.8 0 top
NOREF#36  -  []  59.29 5.86 0 top
NOREF#37  -  []  88.65 71.86 90 top
NOREF#38  -  []  79.23 4.05 0 top
NOREF#39  -  []  26.4 49.91 0 top
NOREF#40  -  []  37.21 19.54 90 top
NOREF#41  -  []  37.82 10.78 0 top
NOREF#42  -  []  85.98 60.16 90 top
NOREF#43  -  []  58.19 8.87 0 top
NOREF#44  -  []  48.64 29.06 90 top
NOREF#45  -  []  70.68 13.72 0 top
NOREF#46  -  []  61.34 40.96 0 top
NOREF#47  -  []  44.45 65.64 90 top
NOREF#48  -  []  2.79 43.56 90 top
NOREF#49  -  []  7.73 29.08 0 top
NOREF#50  -  []  67.55 24.87 0 top
NOREF#51  -  []  69.19 63.26 0 top
NOREF#52  -  []  52.2 65.51 90 top
NOREF#53  -  []  71.39 12.17 0 top
NOREF#54  -  []  74.27 62.34 0 top
NOREF#55  -  []  70.13 13.72 0 top
NOREF#56  -  []  68.6 20.3 90 top
NOREF#57  -  []  83.84 8.27 0 top
NOREF#58  -  []  63.36 69.62 0 top
NOREF#59  -  []  29.32 85.32 90 top
NOREF#60  -  []  18.01 68.72 0 top
NOREF#61  -  []  49.02 9.51 90 top
NOREF#62  -  []  90.57 56.75 90 top
NOREF#63  -  []  60.11 52.36 0 top
NOREF#64  -  []  56.75 50.16 0 top
NOREF#65  -  []  17.29 54.63 0 top
NOREF#66  -  []  2.79 43.56 90 top
NOREF#67  -  []  46.74 58.13 90 top
NOREF#68  -  []  48.73 47.48 0 top
NOREF#69  -  []  54.21 66.44 0 top
NOREF#70  -  []  92.19 81.17 90 top
NOREF#71  -  []  11.28 46.23 0 top
NOREF#72  -  []  41.91 47.48 90 top
NOREF#73  -  []  48.55 68.81 90 top
NOREF#74  -  []  60.14 80.1 0 top
NOREF#75  -  []  49.01 65.16 90 top
NOREF#76  -  []  70.72 30.39 0 top
NOREF#77  -  []  43.54 45.3 0 top
NOREF#78  -  []  80.5 15.48 0 top
NOREF#79  -  []  44.18 38.97 0 top
NOREF#80  -  []  85.72 29.95 90 top
NOREF#81  -  []  43.69 65 90 top
NOREF#82  -  []  69.34 10.01 90 top
NOREF#83  -  []  74.29 10.01 90 top
NOREF#84  -  []  37.07 67.42 0 top
NOREF#85  -  []  90.91 21.61 0 top
NOREF#86  -  []  98.04 42.91 90 top
NOREF#87  -  []  54.59 75.8 0 top
NOREF#88  -  []  35.29 27.6 0 top
NOREF#89  -  []  66.28 42.19 0 top
NOREF#90  -  []  38.82 55.99 0 top
NOREF#91  -  []  83.17 5.69 90 top
NOREF#92  -  []  46.46 24.62 0 top
NOREF#93  -  []  50.58 51.49 90 top
NOREF#94  -  []  16.4 41.13 90 top
NOREF#95  -  []  36.94 21.45 0 top
NOREF#96  -  []  73.79 58.65 90 top
NOREF#97  -  []  67.17 26.9 0 top
NOREF#98  -  []  89.89 95.14 0 top
NOREF#99  -  []  94.6 18.41 0 top
NOREF#100  -  []  33.78 16.87 90 top
NOREF#101  -  []  62.5 54.72 0 top
NOREF#102  -  []  94.27 17.58 0 top
NOREF#103  -  []  30.75 84.09 0 top
NOREF#104  -  []  56.5 66.78 90 top
NOREF#105  -  []  53.95 50.31 0 top
NOREF#106  -  []  9.03 37.19 90 top
NOREF#107  -  []  65.77 26.01 0 top
NOREF#108  -  []  63.23 64.75 90 top
NOREF#109  -  []  94.09 71.26 0 top
NOREF#110  -  []  79.61 24.87 0 top
NOREF#111  -  []  51.03 24.62 0 top
NOREF#112  -  []  29.44 85.6 0 top
NOREF#113  -  []  55.9 7.09 0 top
NOREF#114  -  []  66.82 22.59 90 top
NOREF#115  -  []  69.34 8.36 90 top
NOREF#116  -  []  44.81 20.34 0 top
NOREF#117  -  []  49.3 9.38 0 top
NOREF#118  -  []  47.04 58.73 90 top
NOREF#119  -  []  65.77 24.87 0 top
NOREF#120  -  []  44.69 33.25 0 top
NOREF#121  -  []  81.39 7.64 0 top
NOREF#122  -  []  16.74 56.28 0 top
NOREF#123  -  []  35.83 63.9 0 top
NOREF#124  -  []  52.99 51.49 0 top
NOREF#125  -  []  69.74 63.26 0 top
NOREF#126  -  []  -1 47.79 270 top
NOREF#127  -  []  54.47 84.2 0 top
NOREF#128  -  []  17.25 48.62 0 top
NOREF#129  -  []  58.55 43.8 90 top
NOREF#130  -  []  55.63 7.22 90 top
NOREF#131  -  []  44.09 68.54 90 top
NOREF#132  -  []  47.6 23.51 0 top
NOREF#133  -  []  11.41 43.94 0 top
NOREF#134  -  []  68.58 13.82 90 top
NOREF#135  -  []  65.89 26.29 0 top
NOREF#136  -  []  42.14 33.42 0 top
NOREF#137  -  []  90.44 95.14 0 top
NOREF#138  -  []  45.23 38.97 90 top
NOREF#139  -  []  54.21 6.97 0 top
NOREF#140  -  []  83.54 81.42 0 top
NOREF#141  -  []  70.1 73.01 90 top
NOREF#142  -  []  97 63.72 90 top
NOREF#143  -  []  72.24 33.15 0 top
NOREF#144  -  []  11.92 52.68 0 top
NOREF#145  -  []  54.65 60.06 90 top
NOREF#146  -  []  74.53 68.2 0 top
NOREF#147  -  []  44.81 10.52 90 top
NOREF#148  -  []  32.62 34.15 0 top
NOREF#149  -  []  45.87 23.51 0 top
NOREF#150  -  []  7.22 41.77 0 top
NOREF#151  -  []  66.15 44.94 0 top
NOREF#152  -  []  63.23 63.61 0 top
NOREF#153  -  []  78.97 64.39 0 top
NOREF#154  -  []  38.99 32.49 90 top
NOREF#155  -  []  33.51 12.81 0 top
NOREF#156  -  []  38.68 87.98 90 top
NOREF#157  -  []  92.73 88.13 0 top
NOREF#158  -  []  83.57 7.35 90 top
NOREF#159  -  []  4.04 49.17 0 top
NOREF#160  -  []  15 74.27 90 top
NOREF#161  -  []  19.92 43.29 0 top
NOREF#162  -  []  66.24 64.84 90 top
NOREF#163  -  []  24.78 85.32 90 top
NOREF#164  -  []  95.39 61.83 90 top
NOREF#165  -  []  52.81 44.98 0 top
NOREF#166  -  []  49.89 11.16 0 top
NOREF#167  -  []  88.9 19.79 90 top
NOREF#168  -  []  65.64 5.1 0 top
NOREF#169  -  []  60.56 19.68 0 top
NOREF#170  -  []  81.13 9.51 0 top
NOREF#171  -  []  55.24 12.81 90 top
NOREF#172  -  []  36.93 78.11 0 top
NOREF#173  -  []  30.48 83.17 90 top
NOREF#174  -  []  32.53 41.67 0 top
NOREF#175  -  []  65.89 22.86 0 top
NOREF#176  -  []  34.01 11.7 0 top
NOREF#177  -  []  15.48 92.69 0 top
NOREF#178  -  []  58.97 84.2 0 top
NOREF#179  -  []  38.68 80.98 0 top
NOREF#180  -  []  87.08 69.09 0 top
NOREF#181  -  []  63.35 65.02 0 top
NOREF#182  -  []  10.9 47.75 0 top
NOREF#183  -  []  64.63 48.03 0 top
NOREF#184  -  []  28.86 43.97 0 top
NOREF#185  -  []  53.83 46.5 0 top
NOREF#186  -  []  95.86 85.2 0 top
NOREF#187  -  []  18.49 16.26 0 top
NOREF#188  -  []  77.94 70.38 0 top
NOREF#189  -  []  35.79 40.51 0 top
NOREF#190  -  []  28.6 41.67 0 top
NOREF#191  -  []  49.38 43.18 0 top
NOREF#192  -  []  14.49 76.65 90 top
NOREF#193  -  []  90.04 19.79 90 top
NOREF#194  -  []  33.78 14.84 90 top
NOREF#195  -  []  2.79 45.45 90 top
NOREF#196  -  []  96.62 12.28 90 top
NOREF#197  -  []  74.57 12.17 0 top
NOREF#198  -  []  40.81 67.42 90 top
NOREF#199  -  []  35.65 14.56 0 top
NOREF#200  -  []  65.64 50.91 0 top
NOREF#201  -  []  69.83 59.58 0 top
NOREF#202  -  []  64.49 5.1 0 top
NOREF#203  -  []  38.82 56.39 0 top
NOREF#204  -  []  9 41.77 0 top
NOREF#205  -  []  93.58 71.12 0 top
NOREF#206  -  []  63.36 72.5 0 top
NOREF#207  -  []  20.55 48.9 0 top
NOREF#208  -  []  61.49 6.58 90 top
NOREF#209  -  []  57.73 38.81 0 top
NOREF#210  -  []  47.73 74.28 0 top
NOREF#211  -  []  90.79 68.81 90 top
NOREF#212  -  []  79.32 84.2 0 top
NOREF#213  -  []  5.32 81.61 90 top
NOREF#214  -  []  7.98 41.89 0 top
NOREF#215  -  []  49.13 50.55 0 top
NOREF#216  -  []  38.71 60.98 0 top
NOREF#217  -  []  89.64 58.17 0 top
NOREF#218  -  []  62.21 4.05 0 top
NOREF#219  -  []  38.33 60.03 90 top
NOREF#220  -  []  56.62 67.06 0 top
NOREF#221  -  []  -7.08 -7.08 90 top
NOREF#222  -  []  38.95 54.08 0 top
NOREF#223  -  []  37.19 67.69 0 top
NOREF#224  -  []  60.47 34 90 top
NOREF#225  -  []  66.82 26.01 90 top
NOREF#226  -  []  56.5 67.92 0 top
NOREF#227  -  []  73.26 64.75 0 top
NOREF#228  -  []  94.09 70.21 0 top
NOREF#229  -  []  53.06 36.3 0 top
NOREF#230  -  []  29.21 83.17 90 top
NOREF#231  -  []  67.55 20.3 0 top
NOREF#232  -  []  35.29 29.42 0 top
NOREF#233  -  []  78.74 18.78 90 top
NOREF#234  -  []  48.48 44.83 0 top
NOREF#235  -  []  44.18 24.62 0 top
NOREF#236  -  []  95.86 86.25 0 top
NOREF#237  -  []  33.25 27.29 0 top
NOREF#238  -  []  49.02 22.59 90 top
NOREF#239  -  []  118.98 -84.91 0 top
NOREF#240  -  []  56.62 51.03 90 top
NOREF#241  -  []  80.88 59.93 0 top
NOREF#242  -  []  92.43 53.87 0 top
NOREF#243  -  []  83.69 69.83 90 top
NOREF#244  -  []  12.97 52.68 90 top
NOREF#245  -  []  51.44 35.29 90 top
NOREF#246  -  []  91.47 64.81 0 top
NOREF#247  -  []  67.06 51.03 90 top
NOREF#248  -  []  35.77 14.29 0 top
NOREF#249  -  []  66.15 30.99 0 top
NOREF#250  -  []  39.09 10.78 0 top
NOREF#251  -  []  42.65 37.19 0 top
NOREF#252  -  []  30.97 72.24 90 top
NOREF#253  -  []  66.27 70.1 0 top
NOREF#254  -  []  72.88 56.49 90 top
NOREF#255  -  []  93.58 68.58 0 top
NOREF#256  -  []  34.69 62.55 90 top
NOREF#257  -  []  61.07 79.82 90 top
NOREF#258  -  []  90.69 23.36 0 top
NOREF#259  -  []  51.54 60.43 90 top
NOREF#260  -  []  83.72 18.89 90 top
NOREF#261  -  []  33.25 25.51 0 top
NOREF#262  -  []  78.21 15.48 0 top
NOREF#263  -  []  66.15 70.38 0 top
NOREF#264  -  []  41.4 83.25 90 top
NOREF#265  -  []  9.99 39.73 0 top
NOREF#266  -  []  65.89 27.43 0 top
NOREF#267  -  []  51.4 89.53 90 top
NOREF#268  -  []  97.18 43.83 0 top
NOREF#269  -  []  8.74 45.86 0 top
NOREF#270  -  []  66.15 71.52 0 top
NOREF#271  -  []  51.92 65.39 0 top
NOREF#272  -  []  26.27 51.16 0 top
NOREF#273  -  []  32.26 40.75 90 top
NOREF#274  -  []  59.35 49.3 0 top
NOREF#275  -  []  78.85 62.97 0 top
NOREF#276  -  []  8.11 37.47 0 top
NOREF#277  -  []  64.28 65.89 90 top
NOREF#278  -  []  38.68 80.98 90 top
NOREF#279  -  []  43.07 10.78 0 top
NOREF#280  -  []  36.94 49.66 0 top
NOREF#281  -  []  76.31 73.06 0 top
NOREF#282  -  []  5.6 24.79 90 top
NOREF#283  -  []  46.46 74.28 0 top
NOREF#284  -  []  70.41 13.85 90 top
NOREF#285  -  []  66.02 36.94 0 top
NOREF#286  -  []  93.08 86.4 90 top
NOREF#287  -  []  76.47 19.03 0 top
NOREF#288  -  []  66.82 19.16 90 top
NOREF#289  -  []  73.26 65.8 0 top
NOREF#290  -  []  51.89 71.75 90 top
NOREF#291  -  []  51.6 4.73 90 top
NOREF#292  -  []  90.79 69.96 0 top
NOREF#293  -  []  18.43 54.17 90 top
NOREF#294  -  []  72.24 72.88 0 top
NOREF#295  -  []  74.28 70.72 90 top
NOREF#296  -  []  52.7 40.24 90 top
NOREF#297  -  []  43.29 33.42 0 top
NOREF#298  -  []  33.8 23.6 0 top
NOREF#299  -  []  74.53 67.06 0 top
NOREF#300  -  []  60.56 20.83 0 top
NOREF#301  -  []  41.55 32.37 0 top
NOREF#302  -  []  50.06 50.27 90 top
NOREF#303  -  []  30.59 37.96 0 top
NOREF#304  -  []  79.99 9.51 0 top
NOREF#305  -  []  9.42 46.44 90 top
NOREF#306  -  []  93.07 81.26 0 top
NOREF#307  -  []  8.65 28.81 90 top
NOREF#308  -  []  75.26 26.58 90 top
NOREF#309  -  []  0 0 0 top
NOREF#310  -  []  74.15 73.39 90 top
NOREF#311  -  []  93.07 80.12 90 top
NOREF#312  -  []  79.23 5.1 0 top
NOREF#313  -  []  33.15 10.78 90 top
NOREF#314  -  []  94.51 68.31 90 top
NOREF#315  -  []  92.71 52.94 90 top
NOREF#316  -  []  70.21 32.11 0 top
NOREF#317  -  []  62.08 47.88 0 top
NOREF#318  -  []  32.78 12.83 0 top
NOREF#319  -  []  78.99 9.63 90 top
NOREF#320  -  []  35.67 16.74 0 top
NOREF#321  -  []  44.7 32.49 90 top
NOREF#322  -  []  62.09 39.86 0 top
NOREF#323  -  []  39.1 63.14 0 top
NOREF#324  -  []  20.55 47.75 0 top
NOREF#325  -  []  53.34 36.43 90 top
NOREF#326  -  []  53.95 44.98 0 top
NOREF#327  -  []  35.67 40.79 0 top
NOREF#328  -  []  51.69 38.97 90 top
NOREF#329  -  []  7.33 43.56 0 top
NOREF#330  -  []  95.87 77.34 0 top
NOREF#331  -  []  9.03 41.89 90 top
NOREF#332  -  []  53.57 24.27 0 top
NOREF#333  -  []  7.33 43.16 90 top
NOREF#334  -  []  38.33 70.63 0 top
NOREF#335  -  []  38.12 67.42 90 top
NOREF#336  -  []  76.09 12.17 0 top
NOREF#337  -  []  42.04 21.32 90 top
NOREF#338  -  []  28.32 40.75 90 top
NOREF#339  -  []  68.31 5.82 0 top
NOREF#340  -  []  15.46 18.8 0 top
NOREF#341  -  []  32.87 90.17 0 top
NOREF#342  -  []  67.29 39.48 0 top
NOREF#343  -  []  39.22 62.87 0 top
NOREF#344  -  []  41.17 22.24 0 top
NOREF#345  -  []  51.96 38.84 0 top
NOREF#346  -  []  34.43 39.09 90 top
NOREF#347  -  []  48.15 23.51 0 top
NOREF#348  -  []  20.55 50.67 0 top
NOREF#349  -  []  66.91 62.21 0 top
NOREF#350  -  []  43.94 10.9 90 top
NOREF#351  -  []  44.45 22.59 90 top
NOREF#352  -  []  10.27 40.89 0 top
NOREF#353  -  []  15.54 89.55 0 top
NOREF#354  -  []  66.27 67.82 0 top
NOREF#355  -  []  80.01 60.05 90 top
NOREF#356  -  []  54.46 63.64 0 top
NOREF#357  -  []  35.67 18.44 0 top
NOREF#358  -  []  84.18 27.5 90 top
NOREF#359  -  []  29.37 94.47 90 top
NOREF#360  -  []  51.6 4.73 0 top
NOREF#361  -  []  77.98 27.29 90 top
NOREF#362  -  []  56.75 58.82 0 top
NOREF#363  -  []  67.54 95.39 0 top
NOREF#364  -  []  49.16 74.31 0 top
NOREF#365  -  []  30.72 37.11 0 top
NOREF#366  -  []  58.12 38.42 0 top
NOREF#367  -  []  42.91 54.7 90 top
NOREF#368  -  []  54.97 12.68 0 top
NOREF#369  -  []  32.75 88.75 90 top
NOREF#370  -  []  48.15 67.16 90 top
NOREF#371  -  []  16.74 54.63 0 top
NOREF#372  -  []  45.45 55.21 90 top
NOREF#373  -  []  32.86 32.75 90 top
NOREF#374  -  []  78.46 18.65 0 top
NOREF#375  -  []  0.6 27.25 0 top
NOREF#376  -  []  84.61 38.81 90 top
NOREF#377  -  []  48.75 25.67 0 top
NOREF#378  -  []  70.97 58.53 0 top
NOREF#379  -  []  88.41 28.05 0 top
NOREF#380  -  []  91.19 24.62 90 top
NOREF#381  -  []  68.09 95.39 0 top
NOREF#382  -  []  76.43 27.16 0 top
NOREF#383  -  []  94.76 54.46 90 top
NOREF#384  -  []  83.42 69.71 0 top
NOREF#385  -  []  56.75 65.39 0 top
NOREF#386  -  []  46.74 22.59 90 top
NOREF#387  -  []  66.42 39.6 90 top
NOREF#388  -  []  19.92 43.29 90 top
NOREF#389  -  []  93.07 80.67 0 top
NOREF#390  -  []  43.54 45.3 90 top
NOREF#391  -  []  33.42 11.7 0 top
NOREF#392  -  []  32.75 89.9 0 top
NOREF#393  -  []  44.69 35.67 0 top
NOREF#394  -  []  63.35 63.88 0 top
NOREF#395  -  []  34.42 34.27 90 top
NOREF#396  -  []  69.83 60.68 0 top
NOREF#397  -  []  39.36 46.24 0 top
NOREF#398  -  []  53.83 45.45 0 top
NOREF#399  -  []  49.04 95.27 0 top
NOREF#400  -  []  47.01 65.51 0 top
NOREF#401  -  []  59.54 39.61 0 top
NOREF#402  -  []  35.67 95.39 0 top
NOREF#403  -  []  68.31 13.7 0 top
NOREF#404  -  []  52.18 50.42 0 top
NOREF#405  -  []  38.82 55.99 90 top
NOREF#406  -  []  37.97 63.73 90 top
NOREF#407  -  []  57.04 8.87 0 top
NOREF#408  -  []  44.72 65.51 0 top
NOREF#409  -  []  51.03 25.67 0 top
NOREF#410  -  []  54.65 60.06 90 top
NOREF#411  -  []  77.62 15.48 0 top
NOREF#412  -  []  19.96 11.41 0 top
NOREF#413  -  []  36.81 50.65 0 top
NOREF#414  -  []  68.58 73.01 90 top
NOREF#415  -  []  58.19 6.97 0 top
NOREF#416  -  []  74.28 72.41 0 top
NOREF#417  -  []  51.8 66.53 90 top
NOREF#418  -  []  32.73 12.43 90 top
NOREF#419  -  []  66.15 39.48 0 top
NOREF#420  -  []  5.86 17.8 0 top
NOREF#421  -  []  60.4 48.75 90 top
NOREF#422  -  []  80.41 12.17 90 top
NOREF#423  -  []  28.34 17.38 0 top
NOREF#424  -  []  93.45 70.84 90 top
NOREF#425  -  []  21.48 47.48 90 top
NOREF#426  -  []  42.97 64.82 0 top
NOREF#427  -  []  69.45 6.88 0 top
NOREF#428  -  []  65.64 4.05 0 top
NOREF#429  -  []  93.69 67.96 0 top
NOREF#430  -  []  36.92 67.6 90 top
NOREF#431  -  []  4.32 48.24 90 top
NOREF#432  -  []  11.92 71.73 0 top
NOREF#433  -  []  67.29 27.18 0 top
NOREF#434  -  []  51.02 59.18 0 top
NOREF#435  -  []  54.48 67.16 90 top
NOREF#436  -  []  93.34 59.92 90 top
NOREF#437  -  []  57.91 9 90 top
NOREF#438  -  []  56.5 50.53 90 top
NOREF#439  -  []  61.83 37.93 90 top
NOREF#440  -  []  79.61 18.65 0 top
NOREF#441  -  []  -7.08 -7.08 90 top
NOREF#442  -  []  27.34 98.27 0 top
NOREF#443  -  []  55.9 8.87 0 top
NOREF#444  -  []  84.09 81.42 0 top
NOREF#445  -  []  8.65 27.41 90 top
NOREF#446  -  []  36.72 39.09 90 top
NOREF#447  -  []  78.38 13.7 0 top
NOREF#448  -  []  80.88 60.98 0 top
NOREF#449  -  []  71.14 6.88 0 top
NOREF#450  -  []  91.19 80.6 90 top
NOREF#451  -  []  33.8 25.51 0 top
NOREF#452  -  []  16.74 67.67 0 top
NOREF#453  -  []  41.09 61.13 0 top
NOREF#454  -  []  89.64 25.54 0 top
NOREF#455  -  []  12.05 54.23 0 top
NOREF#456  -  []  33.51 40.51 0 top
NOREF#457  -  []  53.57 40.11 0 top
NOREF#458  -  []  43.03 25.67 0 top
NOREF#459  -  []  92.69 23.37 0 top
NOREF#460  -  []  63.23 65.3 0 top
NOREF#461  -  []  66.82 23.73 90 top
NOREF#462  -  []  53.06 28.94 0 top
NOREF#463  -  []  52.62 58.78 90 top
NOREF#464  -  []  49.26 42.91 90 top
NOREF#465  -  []  35.79 18.16 0 top
NOREF#466  -  []  69.72 5.95 90 top
NOREF#467  -  []  73 5.03 0 top
NOREF#468  -  []  94.72 31.5 0 top
NOREF#469  -  []  5.17 25.04 0 top
NOREF#470  -  []  67.55 23.73 0 top
NOREF#471  -  []  17.38 75.04 0 top
NOREF#472  -  []  21.82 45.58 0 top
NOREF#473  -  []  37.74 80.44 90 top
NOREF#474  -  []  77.72 23.6 90 top
NOREF#475  -  []  -7.08 -7.08 90 top
NOREF#476  -  []  40.62 22.24 0 top
NOREF#477  -  []  3.19 99.77 0 top
NOREF#478  -  []  31.98 41.67 0 top
NOREF#479  -  []  63.36 71.9 0 top
NOREF#480  -  []  14.46 22.21 0 top
NOREF#481  -  []  20.45 22.33 90 top
NOREF#482  -  []  74.78 14.75 0 top
NOREF#483  -  []  60.43 21.1 0 top
NOREF#484  -  []  29.89 44.07 0 top
NOREF#485  -  []  36.94 19.41 0 top
NOREF#486  -  []  52.79 57.13 90 top
NOREF#487  -  []  54.84 54.75 0 top
NOREF#488  -  []  12.55 8.16 0 top
NOREF#489  -  []  61.58 70.49 0 top
NOREF#490  -  []  69.32 12.3 0 top
NOREF#491  -  []  76.82 84.2 90 top
NOREF#492  -  []  65.83 13.38 90 top
NOREF#493  -  []  51.8 66.53 0 top
NOREF#494  -  []  85.45 27.5 90 top
NOREF#495  -  []  96.14 85.32 90 top
NOREF#496  -  []  41 58.13 90 top
NOREF#497  -  []  3.32 86.11 0 top
NOREF#498  -  []  44.72 23.51 0 top
NOREF#499  -  []  5.59 16.87 90 top
NOREF#500  -  []  51.94 61.7 90 top
NOREF#501  -  []  13.19 79.55 0 top
NOREF#502  -  []  48.03 17.8 0 top
NOREF#503  -  []  48.75 9.38 0 top
NOREF#504  -  []  5.31 17.8 0 top
NOREF#505  -  []  66.24 64.84 0 top
NOREF#506  -  []  66.15 68.09 0 top
NOREF#507  -  []  78.21 70.51 90 top
NOREF#508  -  []  71.52 95.39 0 top
NOREF#509  -  []  41.4 81.25 90 top
NOREF#510  -  []  63.52 9.25 0 top
NOREF#511  -  []  55.39 54.75 0 top
NOREF#512  -  []  79.63 15.6 90 top
NOREF#513  -  []  29.32 85.32 0 top
NOREF#514  -  []  79.73 59.93 0 top
NOREF#515  -  []  75.09 28.45 90 top
NOREF#516  -  []  46.84 29.34 0 top
NOREF#517  -  []  94.51 69.58 90 top
NOREF#518  -  []  70.38 59.58 0 top
NOREF#519  -  []  79.9 62.97 90 top
NOREF#520  -  []  31.84 44.07 90 top
NOREF#521  -  []  26.4 51.44 0 top
NOREF#522  -  []  96.63 43.83 0 top
NOREF#523  -  []  87.08 69.49 90 top
NOREF#524  -  []  58.44 5.06 90 top
NOREF#525  -  []  56.49 8.87 0 top
NOREF#526  -  []  68.33 62.34 90 top
NOREF#527  -  []  63.75 16.24 90 top
NOREF#528  -  []  21.48 48.62 90 top
NOREF#529  -  []  40.41 32.37 0 top
NOREF#530  -  []  24.51 36.05 90 top
NOREF#531  -  []  101 8.47 90 top
NOREF#532  -  []  10.16 44.94 90 top
NOREF#533  -  []  66.91 63.26 0 top
NOREF#534  -  []  85.06 47.04 90 top
NOREF#535  -  []  37.45 55.6 90 top
NOREF#536  -  []  59.29 4.81 0 top
NOREF#537  -  []  68.6 23.73 90 top
NOREF#538  -  []  23.01 36.97 0 top
NOREF#539  -  []  43.56 32.49 90 top
NOREF#540  -  []  87 28.17 90 top
NOREF#541  -  []  68.05 63.26 0 top
NOREF#542  -  []  15.6 88.26 0 top
NOREF#543  -  []  70.34 32.38 0 top
NOREF#544  -  []  36.3 58.84 0 top
NOREF#545  -  []  51.16 36.21 0 top
NOREF#546  -  []  68.6 75.17 0 top
NOREF#547  -  []  44.81 35.94 0 top
NOREF#548  -  []  87.27 28.05 0 top
NOREF#549  -  []  93.45 69.57 0 top
NOREF#550  -  []  23.86 84.33 0 top
NOREF#551  -  []  55.52 12.68 0 top
NOREF#552  -  []  66.02 30.71 0 top
NOREF#553  -  []  39.2 67.82 0 top
NOREF#554  -  []  35.65 14.01 90 top
NOREF#555  -  []  12.97 56.49 90 top
NOREF#556  -  []  69.96 60.96 0 top
NOREF#557  -  []  38.33 69.58 0 top
NOREF#558  -  []  53.57 25.38 0 top
NOREF#559  -  []  12.84 78.1 90 top
NOREF#560  -  []  52.05 50.14 0 top
NOREF#561  -  []  94.47 84.6 0 top
NOREF#562  -  []  63.35 67.31 0 top
NOREF#563  -  []  90.91 20.56 0 top
NOREF#564  -  []  9.88 44.81 0 top
NOREF#565  -  []  40.62 20.46 0 top
NOREF#566  -  []  48.62 17.8 0 top
NOREF#567  -  []  74.78 13.7 0 top
NOREF#568  -  []  63.23 67.03 90 top
NOREF#569  -  []  56.62 68.2 0 top
NOREF#570  -  []  1.3 27.25 0 top
NOREF#571  -  []  51.4 83.85 90 top
NOREF#572  -  []  62 66.95 0 top
NOREF#573  -  []  89.66 29.95 90 top
NOREF#574  -  []  32 38.08 90 top
NOREF#575  -  []  90.93 29.95 90 top
NOREF#576  -  []  15.98 80.77 0 top
NOREF#577  -  []  39.37 10.9 90 top
NOREF#578  -  []  66.15 45.99 0 top
NOREF#579  -  []  49.76 17.8 0 top
NOREF#580  -  []  50.93 30.84 90 top
NOREF#581  -  []  74.4 69.72 0 top
NOREF#582  -  []  47.88 24.75 90 top
NOREF#583  -  []  43.03 24.62 0 top
NOREF#584  -  []  52.18 12.21 0 top
NOREF#585  -  []  12.32 86.11 90 top
NOREF#586  -  []  74.06 59.58 0 top
NOREF#587  -  []  45.32 30.71 90 top
NOREF#588  -  []  66.82 27.16 90 top
NOREF#589  -  []  91.04 82.53 90 top
NOREF#590  -  []  48.73 47.88 0 top
NOREF#591  -  []  80.26 9.63 90 top
NOREF#592  -  []  64.41 70.21 90 top
NOREF#593  -  []  127.81 79.41 90 top
NOREF#594  -  []  42.42 32.49 90 top
NOREF#595  -  []  57.48 80.06 0 top
NOREF#596  -  []  94.47 62.1 0 top
NOREF#597  -  []  47.6 25.67 0 top
NOREF#598  -  []  63.48 72.77 0 top
NOREF#599  -  []  46.72 29.61 0 top
NOREF#600  -  []  44.45 24.75 90 top
NOREF#601  -  []  74.4 67.92 90 top
NOREF#602  -  []  12.05 69.47 0 top
NOREF#603  -  []  48.01 74.4 90 top
NOREF#604  -  []  54.48 65.51 90 top
NOREF#605  -  []  40.89 21.32 90 top
NOREF#606  -  []  43.58 23.51 0 top
NOREF#607  -  []  78.97 66.68 0 top
NOREF#608  -  []  76.31 14.75 0 top
NOREF#609  -  []  60.02 80.37 0 top
NOREF#610  -  []  91.69 86.47 90 top
NOREF#611  -  []  74.78 13.7 0 top
NOREF#612  -  []  75.82 12.3 90 top
NOREF#613  -  []  43.67 10.78 0 top
NOREF#614  -  []  0 19.47 0 top
NOREF#615  -  []  13.95 73.13 90 top
NOREF#616  -  []  14.31 43.94 90 top
NOREF#617  -  []  79.61 57.81 0 top
NOREF#618  -  []  42.52 10.78 0 top
NOREF#619  -  []  77.11 21.06 0 top
NOREF#620  -  []  51.41 38.84 0 top
NOREF#621  -  []  40.46 62.04 90 top
NOREF#622  -  []  45.32 25.67 0 top
NOREF#623  -  []  62.21 10.78 0 top
NOREF#624  -  []  54 5.03 0 top
NOREF#625  -  []  89.26 80.77 0 top
NOREF#626  -  []  33.53 23.73 90 top
NOREF#627  -  []  26.78 91.84 0 top
NOREF#628  -  []  72.92 10.94 0 top
NOREF#629  -  []  64.88 35.81 0 top
NOREF#630  -  []  65.77 19.16 0 top
NOREF#631  -  []  78.72 9.51 0 top
NOREF#632  -  []  93.58 69.85 0 top
NOREF#633  -  []  14.08 36.97 0 top
NOREF#634  -  []  45.43 61.34 0 top
NOREF#635  -  []  45.59 29.06 90 top
NOREF#636  -  []  41.87 55.95 90 top
NOREF#637  -  []  72.37 59.58 0 top
NOREF#638  -  []  35.56 62.97 90 top
NOREF#639  -  []  74.28 69.45 0 top
NOREF#640  -  []  75.54 10.94 0 top
NOREF#641  -  []  12.59 48.62 0 top
NOREF#642  -  []  36.69 63.5 90 top
NOREF#643  -  []  50.16 22.59 90 top
NOREF#644  -  []  53.2 34.78 0 top
NOREF#645  -  []  37.85 60.05 90 top
NOREF#646  -  []  53.61 28.94 0 top
NOREF#647  -  []  74.29 12.3 90 top
NOREF#648  -  []  13.95 74.27 0 top
NOREF#649  -  []  15.35 41.68 0 top
NOREF#650  -  []  93.71 54.46 0 top
NOREF#651  -  []  81.28 24.36 90 top
NOREF#652  -  []  75.06 13.82 90 top
NOREF#653  -  []  65.91 51.03 90 top
NOREF#654  -  []  64.75 36.09 0 top
NOREF#655  -  []  60.73 15.55 90 top
NOREF#656  -  []  72.16 13.7 0 top
NOREF#657  -  []  55.12 53.83 90 top
NOREF#658  -  []  55.1 20.57 0 top
NOREF#659  -  []  85.09 67.4 90 top
NOREF#660  -  []  28.34 0.31 90 top
NOREF#661  -  []  12.05 52.96 0 top
NOREF#662  -  []  22.33 40.36 0 top
NOREF#663  -  []  90.13 67.16 0 top
NOREF#664  -  []  56.11 12.68 0 top
NOREF#665  -  []  56.62 49.66 0 top
NOREF#666  -  []  5.46 41.56 90 top
NOREF#667  -  []  44.69 12.85 0 top
NOREF#668  -  []  20.96 39.86 90 top
NOREF#669  -  []  79.35 15.48 0 top
NOREF#670  -  []  48.49 95.27 0 top
NOREF#671  -  []  41.36 46.24 90 top
NOREF#672  -  []  53.09 44.05 90 top
NOREF#673  -  []  50.02 67.71 0 top
NOREF#674  -  []  32.75 87.48 90 top
NOREF#675  -  []  94.19 100 0 top
NOREF#676  -  []  7.49 41.89 90 top
NOREF#677  -  []  15.37 74.67 0 top
NOREF#678  -  []  44.94 20.07 0 top
NOREF#679  -  []  77.45 24.53 0 top
NOREF#680  -  []  45.32 28.94 0 top
NOREF#681  -  []  81 24.24 0 top
NOREF#682  -  []  5.6 22.2 90 top
NOREF#683  -  []  44.69 34.52 0 top
NOREF#684  -  []  53.85 40.24 90 top
NOREF#685  -  []  19.41 11.41 0 top
NOREF#686  -  []  73.13 13.7 0 top
NOREF#687  -  []  48.48 44.43 0 top
NOREF#688  -  []  51.54 60.98 0 top
NOREF#689  -  []  64.16 7.64 0 top
NOREF#690  -  []  62.26 40.68 90 top
NOREF#691  -  []  37.21 21.57 90 top
NOREF#692  -  []  49 50.27 0 top
NOREF#693  -  []  57.39 5.06 0 top
NOREF#694  -  []  47.01 63.86 0 top
NOREF#695  -  []  61.32 72.5 90 top
NOREF#696  -  []  41.76 22.24 0 top
NOREF#697  -  []  44.01 75.62 0 top
NOREF#698  -  []  61.49 20.55 90 top
NOREF#699  -  []  79.33 13.36 0 top
NOREF#700  -  []  69.51 45.7 90 top
NOREF#701  -  []  47.88 22.59 90 top
NOREF#702  -  []  41.36 63.92 90 top
NOREF#703  -  []  35.28 63.9 0 top
NOREF#704  -  []  94.76 19.44 0 top
NOREF#705  -  []  64.41 72.5 90 top
NOREF#706  -  []  50.44 23.51 0 top
NOREF#707  -  []  56.5 49.38 90 top
NOREF#708  -  []  20.43 47.48 0 top
NOREF#709  -  []  67.97 9.42 0 top
NOREF#710  -  []  -702.36 -631.31 0 top
NOREF#711  -  []  41.4 81.25 0 top
NOREF#712  -  []  52.43 41.17 0 top
NOREF#713  -  []  58.17 57.89 90 top
NOREF#714  -  []  65.24 19.88 0 top
NOREF#715  -  []  84.37 17.66 90 top
NOREF#716  -  []  58.27 43.67 0 top
NOREF#717  -  []  33.51 16.75 0 top
NOREF#718  -  []  16.74 55.23 0 top
NOREF#719  -  []  56.75 51.31 0 top
NOREF#720  -  []  10.14 40.62 0 top
NOREF#721  -  []  90.66 27.5 90 top
NOREF#722  -  []  77.83 13.7 0 top
NOREF#723  -  []  41.66 10.9 90 top
NOREF#724  -  []  94.81 20.07 0 top
NOREF#725  -  []  49.02 11.28 90 top
NOREF#726  -  []  78.09 21.82 0 top
NOREF#727  -  []  68.6 16.87 90 top
NOREF#728  -  []  78.85 68.09 0 top
NOREF#729  -  []  42.4 62.97 0 top
NOREF#730  -  []  14.56 38.23 90 top
NOREF#731  -  []  72.37 12.17 0 top
NOREF#732  -  []  89.14 80.5 90 top
NOREF#733  -  []  74.4 66.78 90 top
NOREF#734  -  []  9.03 38.33 90 top
NOREF#735  -  []  12.05 51.69 0 top
NOREF#736  -  []  97.94 38.5 0 top
NOREF#737  -  []  33.93 84.35 0 top
NOREF#738  -  []  83.42 70.76 0 top
NOREF#739  -  []  33.25 23.6 0 top
NOREF#740  -  []  47.75 16.87 90 top
NOREF#741  -  []  35.41 27.88 0 top
NOREF#742  -  []  42.67 63.1 90 top
NOREF#743  -  []  72.79 72.88 0 top
NOREF#744  -  []  49.26 42.91 0 top
NOREF#745  -  []  96.79 6.3 0 top
NOREF#746  -  []  66.57 36.94 0 top
NOREF#747  -  []  74.02 10.94 0 top
NOREF#748  -  []  76.31 13.7 0 top
NOREF#749  -  []  10.27 39.85 90 top
NOREF#750  -  []  67.67 25.15 0 top
NOREF#751  -  []  12.97 51.41 90 top
NOREF#752  -  []  60.11 50.46 0 top
NOREF#753  -  []  51.31 24.75 90 top
NOREF#754  -  []  68.85 72.88 0 top
NOREF#755  -  []  72.14 31.6 90 top
NOREF#756  -  []  65.91 4.17 90 top
NOREF#757  -  []  52.33 17.69 0 top
NOREF#758  -  []  59.05 12.81 90 top
NOREF#759  -  []  93.2 80.39 0 top
NOREF#760  -  []  100 0 90 top
NOREF#761  -  []  9.27 41.89 90 top
NOREF#762  -  []  53.8 52.6 90 top
NOREF#763  -  []  78.97 65.53 0 top
NOREF#764  -  []  66.65 67.54 0 top
NOREF#765  -  []  29.89 44.07 0 top
NOREF#766  -  []  22.73 36.05 90 top
NOREF#767  -  []  2.92 71.24 90 top
NOREF#768  -  []  45.43 60.94 0 top
NOREF#769  -  []  61.45 72.77 0 top
NOREF#770  -  []  31.73 39.01 0 top
NOREF#771  -  []  74.4 72.14 0 top
NOREF#772  -  []  20.54 51.8 0 top
NOREF#773  -  []  18.03 81.9 90 top
NOREF#774  -  []  14.84 48.62 0 top
NOREF#775  -  []  45.43 60.94 90 top
NOREF#776  -  []  23.22 89.39 0 top
NOREF#777  -  []  51.31 11.28 90 top
NOREF#778  -  []  51.8 29.99 0 top
NOREF#779  -  []  0.03 36.33 90 top
NOREF#780  -  []  45.32 23.51 0 top
NOREF#781  -  []  51.92 68.22 0 top
NOREF#782  -  []  6.22 24.49 90 top
NOREF#783  -  []  48.48 44.43 90 top
NOREF#784  -  []  76.59 73.19 90 top
NOREF#785  -  []  89.39 27.5 0 top
NOREF#786  -  []  76.31 57.75 0 top
NOREF#787  -  []  76.84 21.19 90 top
NOREF#788  -  []  57.51 6.48 0 top
NOREF#789  -  []  54.47 84.2 90 top
NOREF#790  -  []  41.87 61.9 0 top
NOREF#791  -  []  67.55 27.16 0 top
NOREF#792  -  []  44.68 48.26 0 top
NOREF#793  -  []  48.75 24.62 0 top
NOREF#794  -  []  3.07 46.37 0 top
NOREF#795  -  []  18.43 54.17 90 top
NOREF#796  -  []  36.7 57.24 90 top
NOREF#797  -  []  65.89 19.43 0 top
NOREF#798  -  []  57.64 8.87 0 top
NOREF#799  -  []  50.65 82.61 90 top
NOREF#800  -  []  76.09 10.94 0 top
NOREF#801  -  []  41.76 20.46 0 top
NOREF#802  -  []  0.6 19.74 0 top
NOREF#803  -  []  84.35 47.24 0 top
NOREF#804  -  []  74.02 12.17 0 top
NOREF#805  -  []  13.57 41.13 90 top
NOREF#806  -  []  5.6 22.85 90 top
NOREF#807  -  []  33.51 39.37 0 top
NOREF#808  -  []  37.74 99.74 0 top
